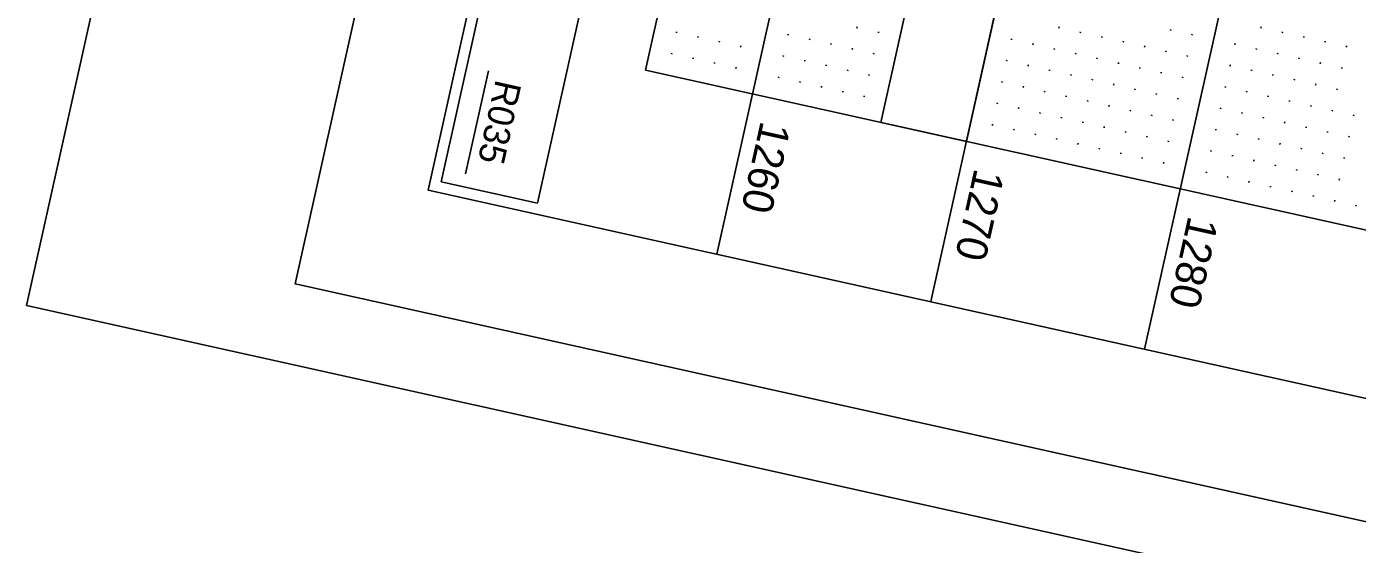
# Model space of a CAD drawing. Extents: x 2149268 to 2150830, y 142155 to 144285.
# Drawn here: x 2149268.2 to 2149571.9, y 142360.6 to 142478.9 of the extents above; entities that cross this region are included whole.
import ezdxf

# ---------------------------------------------------------------- set-up
doc = ezdxf.new("R2010")
doc.units = 0
for name, color, linetype in [('SHT_Plan_Profile_Sheet_Elev_Txt', 7, 'Continuous'), ('SHT_Plan_Profile_Sheet_Txt', 7, 'Continuous'), ('SHT_Plot_Shape_Full', 7, 'Continuous'), ('SHT_Plot_Shape_Half', 7, 'Continuous'), ('SHT_Profile_Grid_Major', 7, 'Continuous'), ('SHT_Profile_Grid_Minor', 7, 'Continuous'), ('SHT_Sheet_Border', 7, 'Continuous'), ('SHT_Standard_Sheet_Lines', 7, 'Continuous')]:
    doc.layers.add(name, color=color, linetype=linetype)

msp = doc.modelspace()

# ---------------------------------------------------------------- linework, layer by layer
at = {"layer": 'SHT_Plot_Shape_Full'}
msp.add_lwpolyline([(2150830.28, 143911.83), (2150439.58, 142154.75), (2149268.19, 142415.21), (2149658.89, 144172.3)], close=True, dxfattribs=at)
at = {"layer": 'SHT_Plot_Shape_Half'}
msp.add_lwpolyline([(2150772.24, 143840.86), (2150403.25, 142181.39), (2149329.47, 142420.15), (2149698.47, 144079.62)], close=True, dxfattribs=at)
at = {"layer": 'SHT_Profile_Grid_Major'}
for p, q in [((2149767.6, 143964.37), (2149425.74, 142426.92)), ((2149816.41, 143953.52), (2149474.54, 142416.07)), ((2149865.21, 143942.67), (2149523.35, 142405.21))]:
    msp.add_line(p, q, dxfattribs=at)
at = {"layer": 'SHT_Profile_Grid_Minor'}
for p, q in [((2149416.55, 142477.75), (2149416.49, 142477.51)), ((2149442.04, 142477.21), (2149441.98, 142476.96)), ((2149457.77, 142478.83), (2149457.71, 142478.59)), ((2149462.65, 142477.74), (2149462.59, 142477.5)), ((2149503.86, 142478.82), (2149503.81, 142478.58)), ((2149508.74, 142477.74), (2149508.69, 142477.49)), ((2149529.35, 142478.28), (2149529.3, 142478.03)), ((2149534.23, 142477.19), (2149534.18, 142476.95)), ((2149549.96, 142478.82), (2149549.91, 142478.57)), ((2149554.84, 142477.73), (2149554.79, 142477.49)), ((2149421.43, 142476.67), (2149421.38, 142476.42)), ((2149426.31, 142475.58), (2149426.26, 142475.34)), ((2149431.19, 142474.49), (2149431.14, 142474.25)), ((2149446.92, 142476.12), (2149446.87, 142475.88)), ((2149451.8, 142475.03), (2149451.75, 142474.79)), ((2149456.68, 142473.95), (2149456.63, 142473.71)), ((2149493.02, 142476.11), (2149492.96, 142475.87)), ((2149497.9, 142475.03), (2149497.84, 142474.78)), ((2149502.78, 142473.94), (2149502.72, 142473.7)), ((2149513.63, 142476.65), (2149513.57, 142476.41)), ((2149518.51, 142475.57), (2149518.45, 142475.32)), ((2149523.39, 142474.48), (2149523.33, 142474.24)), ((2149544, 142475.02), (2149543.94, 142474.78)), ((2149548.88, 142473.94), (2149548.82, 142473.69)), ((2149559.72, 142476.65), (2149559.67, 142476.4)), ((2149564.6, 142475.56), (2149564.55, 142475.32)), ((2149569.48, 142474.48), (2149569.43, 142474.23)), ((2149415.46, 142472.87), (2149415.41, 142472.63)), ((2149420.34, 142471.78), (2149420.29, 142471.54)), ((2149425.23, 142470.7), (2149425.17, 142470.46)), ((2149440.95, 142472.32), (2149440.9, 142472.08)), ((2149445.83, 142471.24), (2149445.78, 142471)), ((2149461.56, 142472.86), (2149461.51, 142472.62)), ((2149491.93, 142471.23), (2149491.88, 142470.99)), ((2149507.66, 142472.86), (2149507.61, 142472.61)), ((2149512.54, 142471.77), (2149512.49, 142471.53)), ((2149517.42, 142470.69), (2149517.37, 142470.44)), ((2149528.27, 142473.4), (2149528.21, 142473.15)), ((2149533.15, 142472.31), (2149533.09, 142472.07)), ((2149553.76, 142472.85), (2149553.7, 142472.61)), ((2149558.64, 142471.77), (2149558.58, 142471.52)), ((2149563.52, 142470.68), (2149563.46, 142470.44)), ((2149430.11, 142469.61), (2149430.05, 142469.37)), ((2149450.71, 142470.15), (2149450.66, 142469.91)), ((2149455.6, 142469.07), (2149455.54, 142468.82)), ((2149460.48, 142467.98), (2149460.42, 142467.74)), ((2149496.81, 142470.15), (2149496.76, 142469.9)), ((2149501.69, 142469.06), (2149501.64, 142468.82)), ((2149506.57, 142467.98), (2149506.52, 142467.73)), ((2149522.3, 142469.6), (2149522.25, 142469.36)), ((2149527.18, 142468.52), (2149527.13, 142468.27)), ((2149542.91, 142470.14), (2149542.86, 142469.9)), ((2149547.79, 142469.06), (2149547.74, 142468.81)), ((2149552.67, 142467.97), (2149552.62, 142467.73)), ((2149568.4, 142469.6), (2149568.35, 142469.35)), ((2149439.87, 142467.44), (2149439.81, 142467.2)), ((2149444.75, 142466.36), (2149444.69, 142466.11)), ((2149449.63, 142465.27), (2149449.58, 142465.03)), ((2149490.85, 142466.35), (2149490.79, 142466.11)), ((2149495.73, 142465.27), (2149495.67, 142465.02)), ((2149511.45, 142466.89), (2149511.4, 142466.65)), ((2149516.34, 142465.81), (2149516.28, 142465.56)), ((2149521.22, 142464.72), (2149521.16, 142464.48)), ((2149532.06, 142467.43), (2149532.01, 142467.19)), ((2149541.82, 142465.26), (2149541.77, 142465.02)), ((2149557.55, 142466.89), (2149557.5, 142466.64)), ((2149562.43, 142465.8), (2149562.38, 142465.56)), ((2149567.31, 142464.72), (2149567.26, 142464.47)), ((2149454.51, 142464.19), (2149454.46, 142463.94)), ((2149459.39, 142463.1), (2149459.34, 142462.86)), ((2149500.61, 142464.18), (2149500.55, 142463.94)), ((2149505.49, 142463.1), (2149505.43, 142462.85)), ((2149510.37, 142462.01), (2149510.32, 142461.77)), ((2149526.1, 142463.64), (2149526.04, 142463.39)), ((2149530.98, 142462.55), (2149530.92, 142462.31)), ((2149546.71, 142464.18), (2149546.65, 142463.93)), ((2149551.59, 142463.09), (2149551.53, 142462.85)), ((2149556.47, 142462.01), (2149556.41, 142461.76)), ((2149489.76, 142461.47), (2149489.71, 142461.23)), ((2149494.64, 142460.39), (2149494.59, 142460.14)), ((2149499.52, 142459.3), (2149499.47, 142459.06)), ((2149515.25, 142460.93), (2149515.2, 142460.68)), ((2149520.13, 142459.84), (2149520.08, 142459.6)), ((2149525.01, 142458.76), (2149524.96, 142458.51)), ((2149540.74, 142460.38), (2149540.69, 142460.14)), ((2149545.62, 142459.3), (2149545.57, 142459.05)), ((2149561.35, 142460.92), (2149561.29, 142460.68)), ((2149566.23, 142459.83), (2149566.17, 142459.59)), ((2149571.11, 142458.75), (2149571.06, 142458.51)), ((2149488.68, 142456.59), (2149488.62, 142456.35)), ((2149493.56, 142455.51), (2149493.5, 142455.26)), ((2149504.4, 142458.22), (2149504.35, 142457.97)), ((2149509.28, 142457.13), (2149509.23, 142456.89)), ((2149514.17, 142456.05), (2149514.11, 142455.8)), ((2149529.89, 142457.67), (2149529.84, 142457.43)), ((2149539.65, 142455.5), (2149539.6, 142455.26)), ((2149550.5, 142458.21), (2149550.45, 142457.97)), ((2149555.38, 142457.12), (2149555.33, 142456.88)), ((2149560.26, 142456.04), (2149560.21, 142455.8)), ((2149498.44, 142454.42), (2149498.38, 142454.18)), ((2149503.32, 142453.33), (2149503.26, 142453.09)), ((2149519.05, 142454.96), (2149518.99, 142454.72)), ((2149523.93, 142453.87), (2149523.87, 142453.63)), ((2149528.81, 142452.79), (2149528.75, 142452.55)), ((2149544.54, 142454.41), (2149544.48, 142454.17)), ((2149549.42, 142453.33), (2149549.36, 142453.08)), ((2149565.14, 142454.95), (2149565.09, 142454.71)), ((2149570.02, 142453.87), (2149569.97, 142453.62)), ((2149508.2, 142452.25), (2149508.14, 142452.01)), ((2149513.08, 142451.16), (2149513.03, 142450.92)), ((2149517.96, 142450.08), (2149517.91, 142449.84)), ((2149538.57, 142450.62), (2149538.51, 142450.37)), ((2149543.45, 142449.53), (2149543.4, 142449.29)), ((2149554.3, 142452.24), (2149554.24, 142452)), ((2149559.18, 142451.16), (2149559.12, 142450.91)), ((2149564.06, 142450.07), (2149564, 142449.83)), ((2149522.84, 142448.99), (2149522.79, 142448.75)), ((2149527.72, 142447.91), (2149527.67, 142447.66)), ((2149548.33, 142448.45), (2149548.28, 142448.2)), ((2149553.21, 142447.36), (2149553.16, 142447.12)), ((2149568.94, 142448.99), (2149568.88, 142448.74)), ((2149537.48, 142445.74), (2149537.43, 142445.49)), ((2149542.36, 142444.65), (2149542.31, 142444.41)), ((2149547.25, 142443.57), (2149547.19, 142443.32)), ((2149558.09, 142446.28), (2149558.04, 142446.03)), ((2149562.97, 142445.19), (2149562.92, 142444.95)), ((2149567.85, 142444.11), (2149567.8, 142443.86)), ((2149552.13, 142442.48), (2149552.07, 142442.24)), ((2149557.01, 142441.4), (2149556.95, 142441.15)), ((2149561.89, 142440.31), (2149561.83, 142440.07)), ((2149566.77, 142439.23), (2149566.71, 142438.98)), ((2149571.65, 142438.14), (2149571.6, 142437.9))]:
    msp.add_line(p, q, dxfattribs=at)
at = {"layer": 'SHT_Sheet_Border'}
msp.add_line((2149409.47, 142468.95), (2149873.15, 142365.85), dxfattribs=at)
for points in [[(2150726.67, 143751.11), (2150384.81, 142213.66), (2149359.84, 142441.57), (2149701.71, 143979.02)], [(2149437.43, 142675.3), (2149415.46, 142680.19), (2149362.83, 142443.47), (2149384.79, 142438.59)], [(2149515.24, 142599.1), (2149495.72, 142603.44), (2149463.16, 142457.01), (2149482.68, 142452.67)]]:
    msp.add_lwpolyline(points, close=True, dxfattribs=at)
msp.add_lwpolyline([(2149433.9, 142694.01), (2149458.31, 142688.59), (2149409.47, 142468.95)], dxfattribs=at)
at = {"layer": 'SHT_Standard_Sheet_Lines'}
msp.add_line((2149373.58, 142468.8), (2149368.35, 142445.25), dxfattribs=at)

# ---------------------------------------------------------------- texts
at = {"layer": 'SHT_Plan_Profile_Sheet_Elev_Txt'}
for s, p in [('1260', (2149435.79, 142457.57)), ('1270', (2149484.59, 142446.72)), ('1280', (2149533.4, 142435.87))]:
    msp.add_text(s, height=7, rotation=257.4638, dxfattribs=at).set_placement(p)
at = {"layer": 'SHT_Plan_Profile_Sheet_Txt'}
msp.add_text('R035', height=6, rotation=257.4638, dxfattribs=at).set_placement((2149375.31, 142467.02))

doc.saveas('drawing.dxf')
